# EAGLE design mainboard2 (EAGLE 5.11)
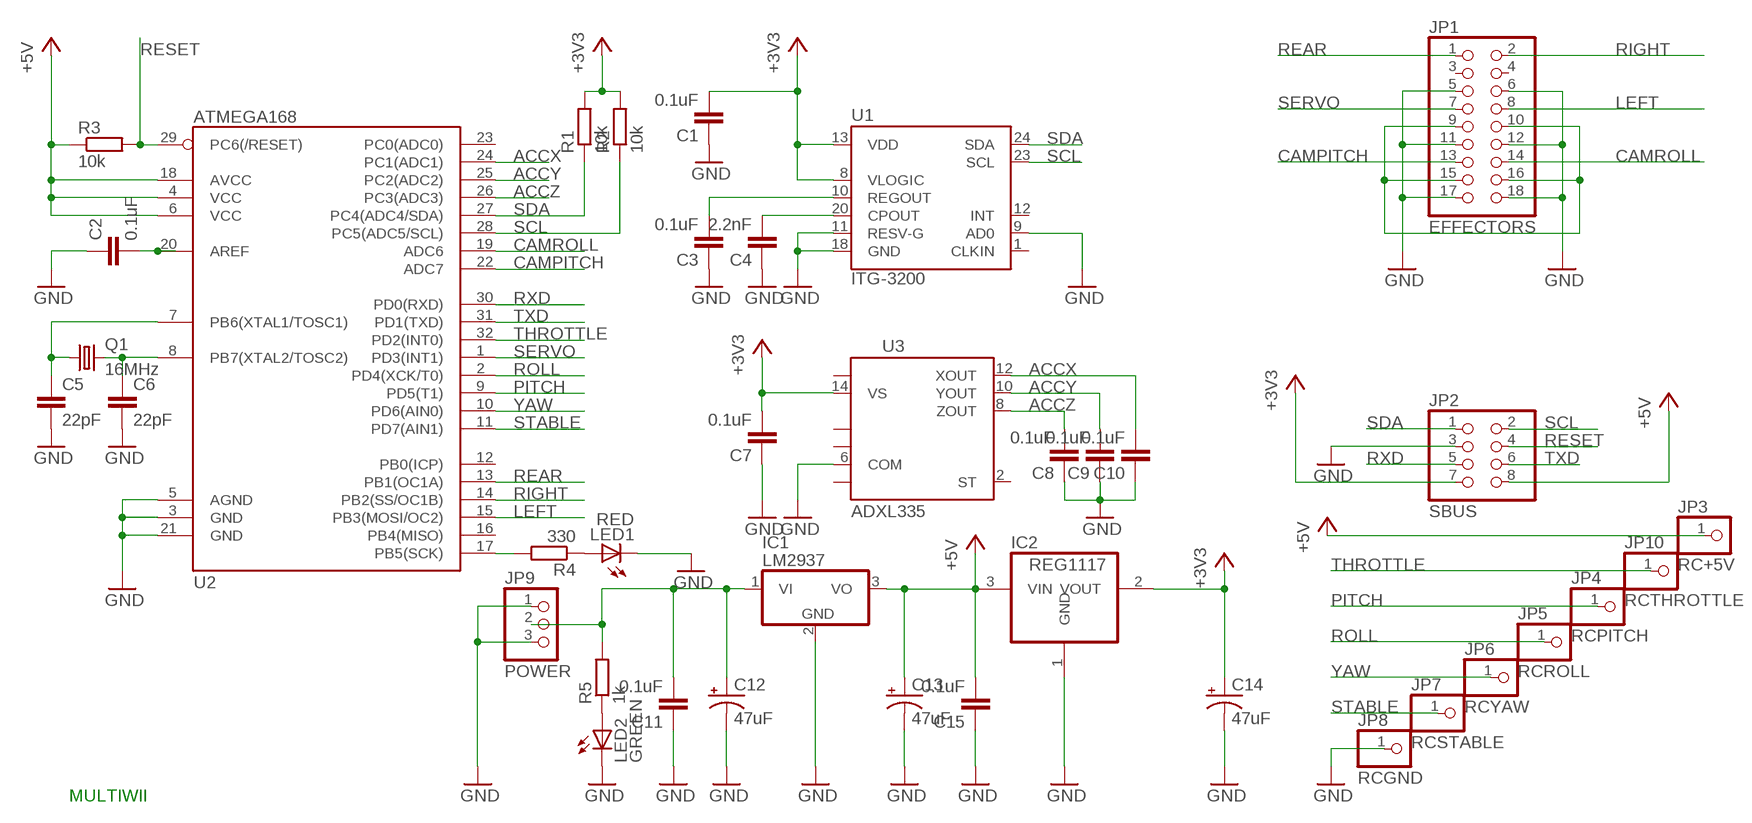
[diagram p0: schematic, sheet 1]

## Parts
C1  0.1uF  C-EUC0805  [C0805]
C2  0.1uF  C-EUC0805  [C0805]
C3  0.1uF  C-EUC0805  [C0805]
C4  2.2nF  C-EUC0805  [C0805]
C5  22pF  C-EUC0805  [C0805]
C6  22pF  C-EUC0805  [C0805]
C7  0.1uF  C-EUC0805  [C0805]
C8  0.1uF  C-EUC0805  [C0805]
C9  0.1uF  C-EUC0805  [C0805]
C10  0.1uF  C-EUC0805  [C0805]
C11  0.1uF  C-EUC0805  [C0805]
C12  47uF  CAP_POL6032  [EIA6032]
C13  47uF  CAP_POL3528  [EIA3528]
C14  47uF  CAP_POL3528  [EIA3528]
C15  0.1uF  C-EUC0805  [C0805]
IC1  LM2937  [TO263-3]
IC2  REG1117  [SOT223]
JP1  EFFECTORS  PINHD-2X9/90  [2X09/90]
JP2  SBUS  PINHD-2X4  [2X04]
JP3  RC+5V  PINHD-1X1  [1X01]
JP4  RCPITCH  PINHD-1X1  [1X01]
JP5  RCROLL  PINHD-1X1  [1X01]
JP6  RCYAW  PINHD-1X1  [1X01]
JP7  RCSTABLE  PINHD-1X1  [1X01]
JP8  RCGND  PINHD-1X1  [1X01]
JP9  POWER  PINHD-1X3/90  [1X03/90]
JP10  RCTHROTTLE  PINHD-1X1  [1X01]
LED1  RED  LEDCHIPLED_0805  [CHIPLED_0805]
LED2  GREEN  LEDCHIPLED_0805  [CHIPLED_0805]
Q1  16MHz  CRYSTALHC49S  [HC49/S]
R1  10k  R-EU_R0805  [R0805]
R2  10k  R-EU_R0805  [R0805]
R3  10k  R-EU_R0805  [R0805]
R4  330  R-EU_R0805  [R0805]
R5  1k  R-EU_R0805  [R0805]
U1  ITG-3200  [QFN-24]
U2  ATMEGA168  [TQFP32-08]
U3  ADXL335  [LFCSP-16]

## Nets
+3V3: C1.2 C7.2 C14.A(+) IC2.2(VOUT) JP2.7 R1.2 R2.2 U1.8(VLOGIC) U1.13(VDD) U3.14(VS)
+5V: C13.A(+) C15.2 IC1.3(VO) IC2.3(VIN) JP2.8 JP3.1 R3.1 U2.4(VCC) U2.6(VCC) U2.18(AVCC)
ACCX: C10.2 U2.24(PC1(ADC1)) U3.12(XOUT)
ACCY: C9.2 U2.25(PC2(ADC2)) U3.10(YOUT)
ACCZ: C8.2 U2.26(PC3(ADC3)) U3.8(ZOUT)
CAMPITCH: JP1.13 U2.22(ADC7)
CAMROLL: JP1.14 U2.19(ADC6)
GND: C1.1 C2.1 C3.1 C4.1 C5.2 C6.2 C7.1 C8.1 C9.1 C10.1 C11.1 C12.P$2(-) C13.C(-) C14.C(-) C15.1 IC1.2(GND) IC2.1(GND) JP1.5 JP1.6 JP1.11 JP1.12 JP1.17 JP1.18 JP2.3 JP8.1 JP9.1 JP9.3 LED1.C LED2.C U1.9(AD0) U1.11(RESV-G) U1.18(GND) U2.3(GND) U2.5(AGND) U2.21(GND) U3.6(COM)
LEFT: JP1.8 U2.15(PB3(MOSI/OC2))
N$1: C6.1 Q1.2 U2.8(PB7(XTAL2/TOSC2))
N$2: C5.1 Q1.1 U2.7(PB6(XTAL1/TOSC1))
N$3: C11.2 C12.P$1(+) IC1.1(VI) JP9.2 R5.2
N$4: C2.2 U2.20(AREF)
N$5: C4.2 U1.20(CPOUT)
N$6: C3.2 U1.10(REGOUT)
N$7: LED2.A R5.1
N$8: JP1.9 JP1.10 JP1.15 JP1.16
N$11: LED1.A R4.1
N$12: R4.2 U2.17(PB5(SCK))
PITCH: JP4.1 U2.9(PD5(T1))
REAR: JP1.1 U2.13(PB1(OC1A))
RESET: JP2.4 R3.2 U2.29(PC6(/RESET))
RIGHT: JP1.2 U2.14(PB2(SS/OC1B))
ROLL: JP5.1 U2.2(PD4(XCK/T0))
RXD: JP2.5 U2.30(PD0(RXD))
SCL: JP2.2 R2.1 U1.23(SCL) U2.28(PC5(ADC5/SCL))
SDA: JP2.1 R1.1 U1.24(SDA) U2.27(PC4(ADC4/SDA))
SERVO: JP1.7 U2.1(PD3(INT1))
STABLE: JP7.1 U2.11(PD7(AIN1))
THROTTLE: JP10.1 U2.32(PD2(INT0))
TXD: JP2.6 U2.31(PD1(TXD))
YAW: JP6.1 U2.10(PD6(AIN0))
Unconnected: JP1.3 JP1.4 U1.1(CLKIN) U1.12(INT) U2.12(PB0(ICP)) U2.16(PB4(MISO)) U2.23(PC0(ADC0)) U3.2(ST) U3.3(COM) U3.5(COM) U3.7(COM) U3.15(VS)

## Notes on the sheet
- MULTIWII

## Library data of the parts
C1-C11 C15 = rcl:C-EU: CAPACITOR, European symbol
C12-C14 = SparkFun:CAP_POL: Capacitor Polarized
IC1 = linear:LM2937: LM2937-2.5, LM2937-3.3 400mA and 500mA Voltage Regulators Source: http://cache.national.com/ds/LM/LM2937-2.5.pdf
IC2 = burr-brown:REG1117: 800mA and 1A Low Dropout (LDO) Positive Regulator 1.8V, 2.5V, 2.85V, 3.3V, 5V, and Adj; MPN: REG1117; OC_FARNELL: 1097566; OC_NEWARK: 14P6981
JP1 = pinhead:PINHD-2X9: PIN HEADER
JP2 = pinhead:PINHD-2X4: PIN HEADER
JP3-JP8 JP10 = pinhead:PINHD-1X1: PIN HEADER
JP9 = pinhead:PINHD-1X3: PIN HEADER
LED1 LED2 = led:LED: LED
Q1 = crystal:CRYSTAL: CRYSTAL; OC_FARNELL: 1667008; OC_NEWARK: unknown
R1-R5 = rcl:R-EU_: RESISTOR, European symbol
U1 = SparkFun:ITG-3200: ITG-3200 3-axis gyro, digital output, qfn24 package
U2 = SparkFun:ATMEGA168
U3 = SparkFun:ADXL335

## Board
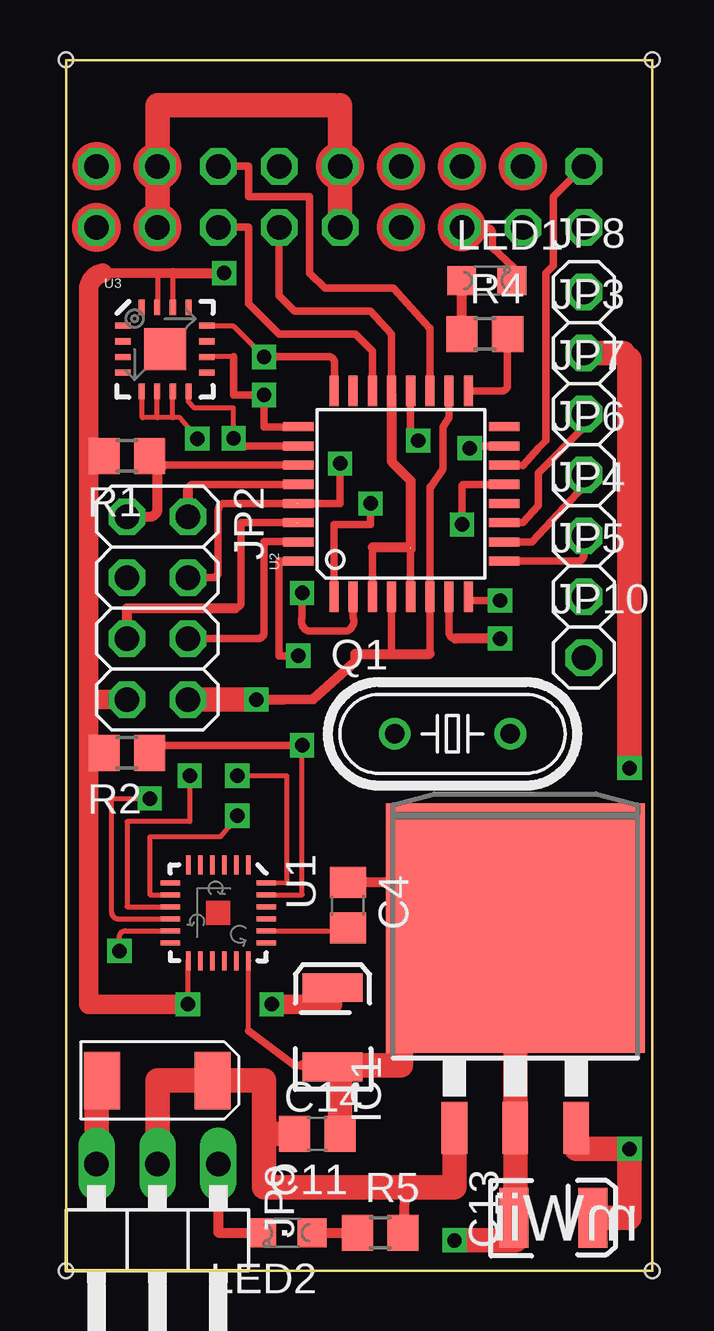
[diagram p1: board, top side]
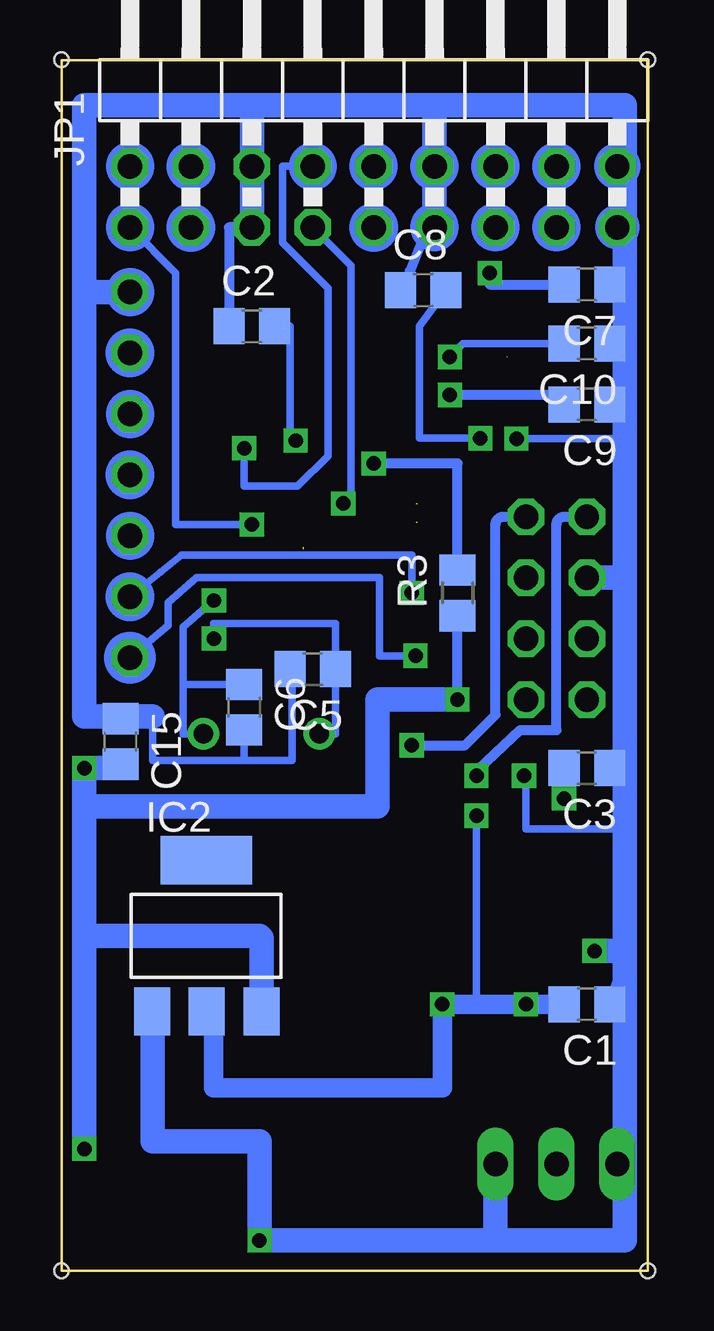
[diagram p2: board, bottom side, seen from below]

Size 24.43 x 50.47 mm. Coordinates in mm from the lower left corner, seen from the top.
Outline: 0,0 24.43,0 24.43,50.47 0,50.47 0,0
Copper layers (1*16): Top 0.035mm / dielectric 1.5mm / Bottom 0.035mm
Design rules "default *": minimum track width 6mil, minimum drill 8mil, track to track 6mil, track to pad 6mil, pad to pad 6mil, via to via 6mil, smd to smd 6mil, copper to edge 0mil, drill to drill 8mil, minimum pad ring 10mil, minimum via ring 8mil, stop-mask expansion 4mil, vias tented up to drill 0mil, thermal gap 10mil
Holes 0.6 mm at 0,50.48 24.45,50.48 24.45,0 0,0

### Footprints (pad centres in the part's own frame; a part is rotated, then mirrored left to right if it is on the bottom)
C0805 = smd 1.3 x 1.5: 1 -0.95,0; 2 0.95,0
EIA6032 = smd 1.5 x 2.4: P$1 -2.3,0; P$2 2.3,0
EIA3528 = smd 1.2 x 2.5: A 1.65,0; C -1.65,0
TO263-3 = smd 1.067 x 2.159: 1 -2.54,-5.791; 2 0,-5.791; 3 2.54,-5.791 | smd 10.8 x 10.41: TAB 0,2.54
SOT223 = smd 1.499 x 2.007: 1 -2.261,-3.15; 2 0.025,-3.15; 3 2.311,-3.15 | smd 3.81 x 2.007: 4 0,3.15
2X09/90 = drill 1.016 octagon: 1 -10.16,-6.35; 2 -10.16,-3.81; 3 -7.62,-6.35; 4 -7.62,-3.81; 5 -5.08,-6.35; 6 -5.08,-3.81; 7 -2.54,-6.35; 8 -2.54,-3.81; 9 0,-6.35; 10 0,-3.81; 11 2.54,-6.35; 12 2.54,-3.81; 13 5.08,-6.35; 14 5.08,-3.81; 15 7.62,-6.35; 16 7.62,-3.81; 17 10.16,-6.35; 18 10.16,-3.81
2X04 = drill 1.016 octagon: 1 -3.81,-1.27; 2 -3.81,1.27; 3 -1.27,-1.27; 4 -1.27,1.27; 5 1.27,-1.27; 6 1.27,1.27; 7 3.81,-1.27; 8 3.81,1.27
1X01 = drill 1.016 octagon: 1 0,0
1X03/90 = drill 1.016 long: 1 -2.54,-3.81; 2 0,-3.81; 3 2.54,-3.81
CHIPLED_0805 = smd 1.2 x 1.2: A 0,-1.05; C 0,1.05
HC49/S = drill 0.813 round: 1 -2.413,0; 2 2.413,0
R0805 = smd 1.3 x 1.5: 1 -0.95,0; 2 0.95,0
QFN-24 = smd 0.8 x 0.203: 1 -2,1.25; 2 -2,0.75; 3 -2,0.25; 4 -2,-0.25; 5 -2,-0.75; 6 -2,-1.25; 13 2,-1.25; 14 2,-0.75; 15 2,-0.25; 16 2,0.25; 17 2,0.75; 18 2,1.25 | smd 0.203 x 0.8: 7 -1.25,-2; 8 -0.75,-2; 9 -0.25,-2; 10 0.25,-2; 11 0.75,-2; 12 1.25,-2; 19 1.25,2; 20 0.75,2; 21 0.25,2; 22 -0.25,2; 23 -0.75,2; 24 -1.25,2
TQFP32-08 = smd 1.27 x 0.381: 1 -4.293,2.8; 2 -4.293,2; 3 -4.293,1.2; 4 -4.293,0.4; 5 -4.293,-0.4; 6 -4.293,-1.2; 7 -4.293,-2; 8 -4.293,-2.8; 17 4.293,-2.8; 18 4.293,-2; 19 4.293,-1.2; 20 4.293,-0.4; 21 4.293,0.4; 22 4.293,1.2; 23 4.293,2; 24 4.293,2.8 | smd 0.381 x 1.27: 9 -2.8,-4.293; 10 -2,-4.293; 11 -1.2,-4.293; 12 -0.4,-4.293; 13 0.4,-4.293; 14 1.2,-4.293; 15 2,-4.293; 16 2.8,-4.293; 25 2.8,4.293; 26 2,4.293; 27 1.2,4.293; 28 0.4,4.293; 29 -0.4,4.293; 30 -1.2,4.293; 31 -2,4.293; 32 -2.8,4.293
LFCSP-16 = smd 1.75 x 1.75: 0 0,0 | smd 0.65 x 0.254: 1 -1.75,0.975; 2 -1.75,0.325; 3 -1.75,-0.325; 4 -1.75,-0.975; 9 1.75,-0.975; 10 1.75,-0.325; 11 1.75,0.325; 12 1.75,0.975 | smd 0.254 x 0.65: 5 -0.975,-1.75; 6 -0.325,-1.75; 7 0.325,-1.75; 8 0.975,-1.75; 13 0.975,1.75; 14 0.325,1.75; 15 -0.325,1.75; 16 -0.975,1.75

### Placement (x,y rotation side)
C1  2.54,11.11 180 bottom
C2  16.51,39.37 0 bottom
C3  2.54,20.95 180 bottom
C4  11.75,15.24 270 top
C5  13.97,25.08 180 bottom
C6  16.83,23.5 270 bottom
C7  2.54,41.12 180 bottom
C8  9.37,40.88 0 bottom
C9  2.54,36.12 180 bottom
C10  2.54,38.66 180 bottom
C11  10.48,5.71 180 top
C12  3.81,7.94 180 top
C13  20.32,2.22 0 top
C14  11.11,10.16 90 top
C15  21.99,22.07 270 bottom
IC1  18.73,11.75 0 top
IC2  18.41,13.97 0 bottom
JP1  11.43,49.85 0 bottom
JP2  3.81,27.62 270 top
JP3  21.59,38.26 0 top
JP4  21.59,30.64 0 top
JP5  21.59,28.1 0 top
JP6  21.59,33.18 0 top
JP7  21.59,35.72 0 top
JP8  21.59,40.8 0 top
JP9  3.81,0.64 180 top
JP10  21.59,25.56 0 top
LED1  17.54,41.27 270 top
LED2  9.21,1.59 90 top
Q1  16.11,22.38 0 top
R1  2.54,33.97 180 top
R2  2.54,21.59 180 top
R3  7.94,28.26 90 bottom
R4  17.46,39.05 0 top
R5  13.1,1.59 0 top
U1  6.35,14.92 270 top
U2  13.97,32.38 90 top
U3  4.13,38.42 0 top

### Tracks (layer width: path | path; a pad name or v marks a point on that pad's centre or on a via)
+3V3  (via drill 0.6)
  Top 0.2: 4.45,41.59 U3.14 | U1.8 3.49,15.67 3.49,18.1 6.43,18.1 v7.14,18.97 | 3.81,41.59 3.81,40.32 | U1.13 5.08,12.92 v5.08,11.11
  Top 0.4: 1.52,41.59 3.81,41.59 4.45,41.59
  Top 0.406: 4.45,41.59 v6.59,41.59 | 0.95,33.97 R1.2 | 0.95,20.95 R2.2 | 11.11,11.11 C14.A
  Top 0.813: 1.52,41.59 arc90 0.95,40.7 0.95,33.97 0.95,23.81 | 0.95,23.81 JP2.7 | 0.95,23.81 0.95,20.95 0.95,11.11 v5.08,11.11 | v8.57,11.11 11.11,11.11
  Bottom 0.305: 7.14,11.11 7.14,14.45 v7.14,18.97
  Bottom 0.406: v6.59,41.59 6.59,41.12 C7.2 | IC2.2 18.1,10.82 18.1,10.79
  Bottom 0.813: C1.2 v5.08,11.11 7.14,11.11 v8.57,11.11 8.57,7.62 18.1,7.62 18.1,10.79 18.1,11.11
+5V  (via drill 0.6)
  Top 0.305: U2.4 arc-90 13.57,28.01 13.57,25.72 | U2.18 arc90 15.95,36.58 15.95,35.56 15.72,35.16 15.72,33.42 15.24,32.7 arc90 15.17,32.63 U2.6 15.17,25.72
  Top 0.406: 23.5,38.01 arc90 23.24,38.26 | 8.95,23.81 v7.94,23.81 9.05,23.81 10.32,23.83 12.06,25.4 12.06,25.72 13.57,25.72 15.17,25.72 | 23.5,26.1 arc90 23.24,26.35 | 21.27,5.08 IC1.3
  Top 1.016: v7.94,23.81 JP2.8 | 23.24,38.26 JP3.1 | 23.5,38.01 23.5,26.1 v23.5,20.95 | C13.A 23.5,2.22 v23.5,5.08 21.27,5.08
  Bottom 0.406: 16.19,13.97 16.1,13.88 | 23.5,13.65 23.18,13.97 | v7.94,23.81 R3.1 | 22.23,21.19 C15.2
  Bottom 1.016: v23.5,5.08 23.5,13.65 23.5,19.37 | 23.5,19.37 v23.5,20.95 22.23,20.95 22.23,21.19 | 16.1,13.88 IC2.3 | 23.18,13.97 16.19,13.97 | 23.5,19.37 11.27,19.37 11.27,23.81 v7.94,23.81
ACCX  (via drill 0.6)
  Top 0.2: v8.26,38.1 6.99,39.37 5.9,39.37 U3.12
  Top 0.3: 11.19,36.81 arc90 U2.24
  Top 0.305: 11.19,36.81 11.19,37.92 arc90 10.86,38.1 v8.26,38.1
  Bottom 0.305: C10.2 7.7,38.66 v8.26,38.1
ACCY  (via drill 0.6)  (1 unrouted)
  Top 0.2: 6.99,38.1 U3.10
  Top 0.3: 9.62,35.16 arc-90 U2.25
  Top 0.305: 9.62,35.16 8.26,35.16 v8.26,36.51 6.99,36.51 6.99,38.1
  Bottom 0.406: 3.51,36.04 C9.2 3.57,36.2 3.49,36.51 v8.26,36.51
ACCZ  (via drill 0.6)
  Top 0.2: 6.99,34.64 v6.99,34.7 6.99,35.97 5.36,35.97 5.1,36.23 U3.8
  Top 0.305: U2.26 7.24,34.38 arc-90 6.99,34.64
  Bottom 0.305: v6.99,34.7 9.53,34.7 9.53,39.37 8.81,40.34 8.02,41.04 C8.2
CAMPITCH
  Top 0.305: U2.22 12.77,38.35 12.06,39.05 8.89,39.05 7.62,40.32 7.62,43.5 JP1.13
CAMROLL  (1 unrouted)
  Top 0.305: JP1.14 7.62,46.04 7.62,44.77 10.16,44.77 10.16,41.59 10.79,40.96 13.65,40.96 15.16,39.29 | U2.19 15.17,39.3
GND  (via drill 0.6)  (1 unrouted)
  Top 0.2: U1.11 2.48,14.17 arc90 2.22,13.92 v2.22,13.34 | U1.9 2.54,15.17 2.54,18.73 5.16,18.73 v5.16,20.64 | U3.6 3.8,35.56 4.76,35.56 v5.48,34.69 | U1.18 7.62,12.92 7.62,10
  Top 0.3: 13.57,36.52 arc90 U2.21 arc90 13.57,36.76 | U2.3 12.78,28.16
  Top 0.305: 12.78,28.16 12.78,30.16 | 14.37,30.08 U2.5 | 13.57,36.76 13.57,39.05 12.7,40.01 9.53,40.01 8.89,40.64 JP1.11 | JP1.5 17.53,43.5 arc-90 17.78,43.24 17.78,42.66 18.65,41.83 LED1.C | 7.62,10 9.53,8.57 9.84,8.57 | 10.16,8.57 11.05,8.57
  Top 0.406: 12.78,30.16 14.29,30.16 arc-90 14.37,30.08 | 14.37,30.16 14.37,32.94 13.57,33.73 13.57,36.52 | 1.27,8.57 C12.P$2 1.83,8.89 2.06,8.89 | C13.C 18.73,2.22 18.73,1.27 | 11.05,8.57 C14.C 11.43,8.2 | LED2.C 6.35,1.59 JP9.1 | C4.1 18.73,16.19 18.73,12.7 | 9.84,8.57 10.16,8.57 13.97,8.57 13.97,12.7 18.73,12.7 | IC1.2 18.73,12.7
  Top 1.016: JP9.3 1.27,8.57 | 18.73,2.22 IC1.2 | 11.43,8.2 C11.1 | v16.19,1.27 18.73,1.27 | 11.43,8.57 13.97,8.57 13.97,9.21
  Bottom 0.305: 16.83,21.27 20.64,21.27 20.64,23.1 | 16.83,21.27 C6.2 | C5.2 14.84,25.32 14.84,21.27 16.83,21.27 | 0.95,18.41 5.08,18.41 5.08,20.64 | 0.95,34.69 v5.48,34.69
  Bottom 0.406: 0.95,38.42 C10.1 | 0.95,36.2 C9.1 | 0.95,40.96 C7.1 | 0.95,20.95 C3.1 | C1.1 1.27,12.06 0.95,11.43 | 20.64,10.5 IC2.1 | JP1.5 17.46,43.5 17.46,40.96 C2.1 | 5.08,20.64 v5.16,20.64 | JP1.11 9.37,43.02 9.92,41.67 C8.1 | 14.84,25.32 15.08,25.32
  Bottom 1.016: JP1.5 JP1.6 16.51,48.58 | JP1.11 JP1.12 8.89,48.58 | 0.95,43.5 0.95,46.04 JP1.18 0.95,46.2 | 0.95,13.34 0.95,18.41 0.95,20.95 0.95,28.89 | 0.95,28.89 0.95,34.69 0.95,36.2 0.95,38.42 0.95,40.96 0.95,43.5 | 0.95,28.89 JP2.3 | 8.89,48.58 16.51,48.58 | 0.95,48.58 8.89,48.58 | 0.95,46.2 0.95,45.8 | 0.95,46.2 0.95,48.58 | 0.95,48.58 | 0.95,43.5 JP1.17 | 16.51,48.58 23.5,48.58 23.5,40.8 | 23.5,40.8 JP8.1 | 0.95,13.34 v2.22,13.34 | 0.95,4.45 0.95,11.43 0.95,13.34 | 0.95,4.45 0.95,1.27 6.35,1.27 | 0.95,4.45 JP9.3 | 6.35,1.27 JP9.1 | 6.35,1.27 v16.19,1.27 16.19,5.4 20.64,5.4 20.64,10.5 | 23.5,40.8 23.5,23.1 21.99,23.1 | 21.99,23.1 20.64,23.1 | 21.99,23.1 C15.1
LEFT  (via drill 0.6)
  Top 0.305: U2.15 16.92,34.38 arc90 v16.83,34.29
  Bottom 0.305: JP1.8 15.24,46.04 15.24,42.86 13.34,40.96 13.34,33.97 14.61,32.7 16.83,32.7 v16.83,34.29
N$1  (via drill 0.6)
  Top 0.3: 16.92,27.94 U2.8
  Top 0.305: v18.1,27.94 16.92,27.94
  Bottom 0.305: 19.37,24.45 17.15,24.45 | 19.37,24.45 19.37,26.83 v18.1,27.94 | Q1.2 19.37,22.38 19.37,24.45
  Bottom 0.406: 17.15,24.45 arc88 C6.1
N$2  (via drill 0.6)
  Top 0.305: U2.7 15.97,26.61 arc90 16.22,26.35
  Top 0.406: v18.1,26.35 16.22,26.35
  Bottom 0.305: v18.1,26.35 18.1,26.99 13.02,26.99 13.02,25.4 13.02,22.38 Q1.1
  Bottom 0.406: C5.1 13.02,25.15 arc-90 13.27,25.4 13.02,25.4
N$3
  Top 0.406: R5.2 14.13,3.49 15.56,3.49
  Top 1.016: JP9.2 3.81,7.94 C12.P$1 8.26,7.94 8.26,5.71 | 8.26,5.71 8.26,3.49 15.56,3.49 16.19,3.49 IC1.1 | 8.26,5.71 C11.2
N$4  (via drill 0.6)
  Top 0.305: U2.20 14.37,34.84 arc90 v14.68,34.61
  Bottom 0.305: v14.68,34.61 14.92,34.61 14.92,35.64 14.92,39.37 C2.2
  Bottom 0.406: C2.2
N$5
  Top 0.2: U1.20 11.43,14.17
  Top 0.406: 11.43,14.17 11.75,14.17 C4.2
N$6  (via drill 0.6)
  Top 0.2: U1.10 2.16,14.67 arc-90 1.91,14.93 1.91,19.68 v3.49,19.68
  Bottom 0.406: C3.2 v3.49,19.68
N$7
  Top 0.406: LED2.A R5.1
N$8
  Top 0.406: 11.18,48.58 arc-90 11.43,48.32 arc-90 11.68,48.58
  Top 1.016: 11.43,48.58 11.43,48.32 JP1.10 JP1.9 | 11.18,48.58 3.81,48.58 JP1.16 JP1.15
N$9
  Top 0.2: 3.17,36.83 3.17,35.56 4.45,35.56 4.45,36.83
N$11
  Top 0.406: LED1.A arc-90 16.51,41.16 R4.1
N$12
  Top 0.305: U2.17 18.16,36.68 arc90 18.41,36.93 R4.2
PITCH
  Top 0.305: U2.9 21.34,29.59 arc90 21.59,29.84 JP4.1
REAR  (via drill 0.6)
  Top 0.305: U2.13 16.59,32.78 arc90 16.51,32.7 v16.51,31.11
  Bottom 0.305: JP1.1 19.68,41.59 19.68,31.11 v16.51,31.11
RESET  (via drill 0.6)  (1 unrouted)
  Top 0.305: U2.29 6.6,31.98 arc90 6.35,31.73 6.35,29.15 arc-90 6.1,28.89 JP2.4 | v11.43,33.66 11.43,31.99 9.6,31.99
  Bottom 0.406: R3.2 7.94,33.66 v11.43,33.66
RIGHT
  Top 0.3: 19.68,34.29 20,34.61
  Top 0.305: JP1.2 20.32,44.77 20.32,41.91 20,41.59 20,34.61 | U2.14 19.05,33.58 19.68,34.29
ROLL  (via drill 0.6)
  Top 0.305: U2.2 11.97,27.24 arc-90 11.72,26.67 10.1,26.67 arc-90 9.84,27.24 v9.84,28.26
  Bottom 0.305: v9.84,28.26 9.84,29.84 19.43,29.84 20.3,29.13 JP5.1
RXD  (1 unrouted)
  Top 0.305: 7.05,27.62 arc90 7.3,27.88 7.3,31.19 9.61,31.19
  Top 0.406: JP2.5 2.54,27.62 7.05,27.62
S$1
  Top 1.016: 18.73,2.54 18.73,12.06
SCL  (via drill 0.6)
  Top 0.2: v9.84,21.91 | U1.23 9.84,15.67 v9.84,21.91
  Top 0.305: U2.28 5.33,32.78 arc90 5.08,32.53 | v9.84,21.91 3.81,21.91 3.81,21.21
  Top 0.406: 5.08,31.26 JP2.2 5.08,32.53 | 3.81,21.91 R2.1
  Bottom 0.406: JP2.2 6.03,31.43 arc-90 6.35,31.11 6.35,23.18 7.62,21.91 v9.84,21.91
SDA  (via drill 0.6)
  Top 0.2: v7.14,20.64 9.21,20.64 9.21,16.19 U1.24
  Top 0.305: 4.06,33.59 U2.27
  Top 0.406: 3.81,33.34 3.81,31.75 arc-90 3.49,31.43 JP2.1 | 3.81,33.34 R1.1 | 3.81,33.34 arc-90 4.06,33.59
  Bottom 0.406: JP2.1 3.49,31.43 arc-90 3.81,31.11 3.81,22.54 5.32,22.54 7.06,20.89 arc90 7.32,20.64 v7.14,20.64
SERVO  (via drill 0.6)
  Top 0.305: U2.1 11.17,31.07 arc-90 11.22,31.11 12.7,31.11 v12.7,31.99
  Bottom 0.305: JP1.7 12.38,41.91 12.38,35 12.38,31.99 v12.7,31.99
STABLE
  Top 0.305: JP7.1 21.59,35.16 19.68,33.26 19.68,31.91 19.05,31.19 U2.11
THROTTLE  (via drill 0.6)
  Top 0.305: U2.32 8.89,29.59 8.89,25.64 v9.68,25.64
  Bottom 0.305: JP10.1 20,26.91 20,27.86 18.81,28.89 11.19,28.89 11.19,25.64 v9.68,25.64
TXD
  Top 0.3: 9.58,30.4 arc-90 U2.31
  Top 0.305: JP2.6 8,26.35 arc90 8.26,26.61 8.26,30.4 9.58,30.4
YAW
  Top 0.305: U2.10 19.43,30.39 21.59,32.7 JP6.1
(copper drawn outside any net)
  shapes: Bottom circle x22, Top circle x10

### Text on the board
_tNames: mWii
